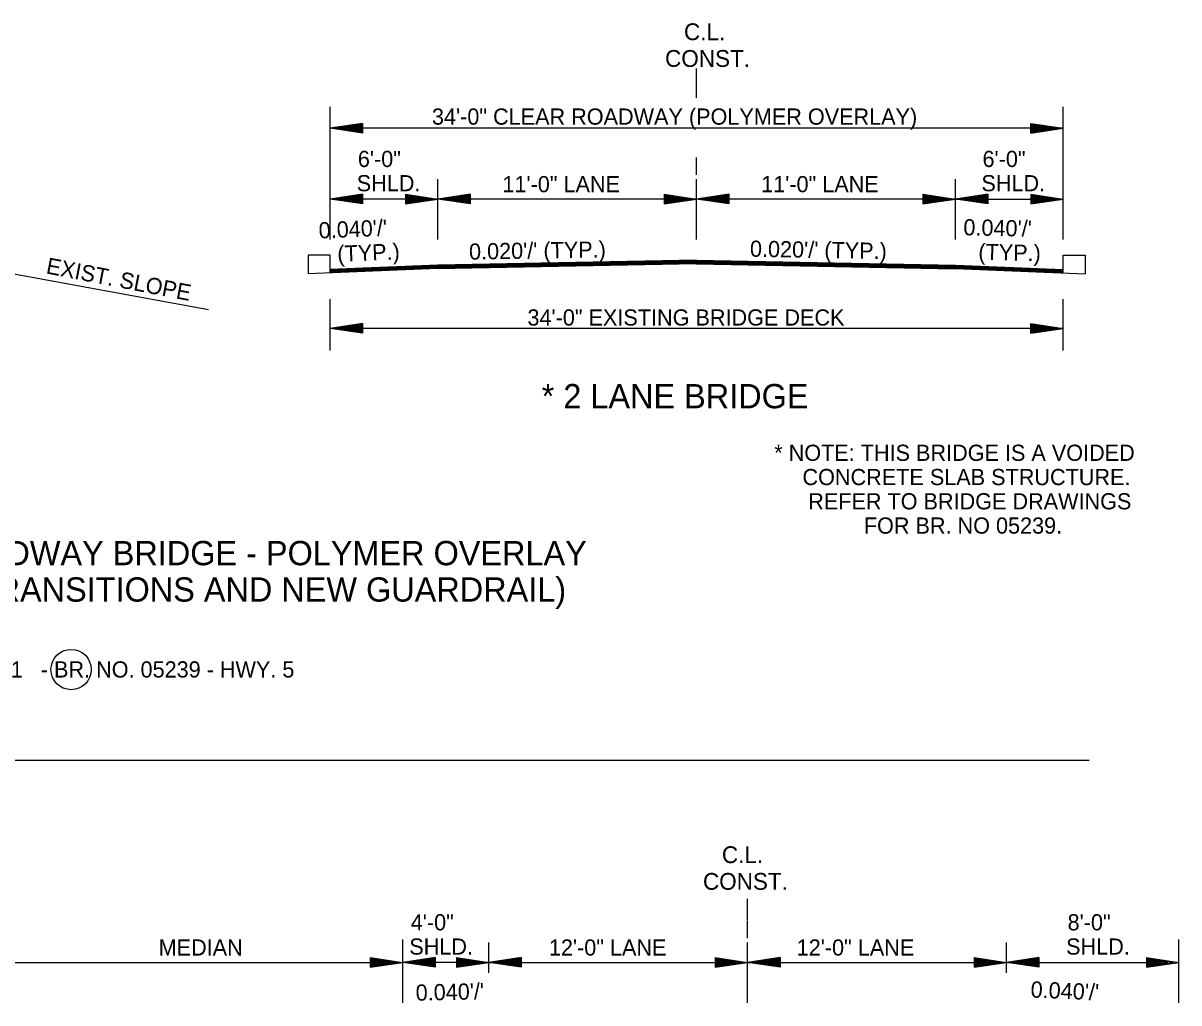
# Model space of a CAD drawing. Extents: x 544199 to 1930787, y -1968972 to 596640.
# Drawn here: x 546713 to 547249, y -1947878 to -1947424 of the extents above; entities that cross this region are included whole.
import ezdxf

# ---------------------------------------------------------------- set-up
doc = ezdxf.new("R2010")
doc.units = 0
doc.layers.add('R_Border', color=7, linetype='Continuous')
doc.layers.add('R_Draft', color=7, linetype='Continuous')

msp = doc.modelspace()

# ---------------------------------------------------------------- linework, layer by layer
at = {"layer": 'R_Border'}
for p, q in [((546845.64, -1947531.28), (546845.64, -1947539.89)), ((546855.81, -1947531.28), (546845.64, -1947531.28)), ((546855.81, -1947539.18), (546855.81, -1947531.28)), ((547195.81, -1947539.18), (547195.81, -1947531.28)), ((547195.81, -1947531.28), (547205.98, -1947531.28)), ((547205.98, -1947531.28), (547205.98, -1947539.89)), ((546249.01, -1947765.5), (547207.84, -1947765.5))]:
    msp.add_line(p, q, dxfattribs=at)
msp.add_circle((546735.71, -1947723.42), 9.34, dxfattribs=at)
at = {"layer": 'R_Draft'}
for p, q in [((547025.81, -1947458.4), (547025.81, -1947444.7)), ((546855.81, -1947524.04), (546855.81, -1947462.55)), ((547195.81, -1947524.04), (547195.81, -1947462.55)), ((546870.81, -1947470.19), (546855.81, -1947472.44)), ((547195.81, -1947472.44), (546855.81, -1947472.44)), ((546870.81, -1947474.69), (546855.81, -1947472.44)), ((546870.81, -1947470.57), (546858.31, -1947472.44)), ((546870.81, -1947474.32), (546858.31, -1947472.44)), ((546870.81, -1947470.95), (546860.89, -1947472.44)), ((546870.81, -1947473.93), (546860.89, -1947472.44)), ((546870.81, -1947471.32), (546863.39, -1947472.44)), ((546870.81, -1947473.56), (546863.39, -1947472.44)), ((546870.81, -1947471.71), (546865.93, -1947472.44)), ((546870.81, -1947473.18), (546865.93, -1947472.44)), ((546870.81, -1947472.09), (546868.44, -1947472.44)), ((546870.81, -1947472.79), (546868.44, -1947472.44)), ((546870.81, -1947470.19), (546870.81, -1947474.69)), ((547195.81, -1947472.44), (546915.81, -1947472.44)), ((547180.81, -1947470.19), (547195.81, -1947472.44)), ((547180.81, -1947474.69), (547180.81, -1947470.19)), ((547180.81, -1947470.57), (547193.3, -1947472.44)), ((547180.81, -1947470.95), (547190.72, -1947472.44)), ((547180.81, -1947471.32), (547188.23, -1947472.44)), ((547180.81, -1947471.71), (547185.68, -1947472.44)), ((547180.81, -1947472.09), (547183.18, -1947472.44)), ((547180.81, -1947474.69), (547195.81, -1947472.44)), ((547180.81, -1947473.17), (547185.68, -1947472.44)), ((547180.81, -1947473.93), (547190.72, -1947472.44)), ((547180.81, -1947474.32), (547193.3, -1947472.44)), ((547180.81, -1947473.56), (547188.23, -1947472.44)), ((547180.81, -1947472.79), (547183.18, -1947472.44)), ((547025.81, -1947493.96), (547025.81, -1947485.98)), ((546905.81, -1947524.04), (546905.81, -1947496.09)), ((547025.81, -1947524.04), (547025.81, -1947496.09)), ((547145.81, -1947524.04), (547145.81, -1947496.09)), ((546870.81, -1947503.02), (546855.81, -1947505.27)), ((546905.81, -1947505.27), (546855.81, -1947505.27)), ((546870.81, -1947507.52), (546855.81, -1947505.27)), ((546870.81, -1947503.4), (546858.31, -1947505.27)), ((546870.81, -1947507.15), (546858.31, -1947505.27)), ((546870.81, -1947503.78), (546860.89, -1947505.27)), ((546870.81, -1947506.77), (546860.89, -1947505.27)), ((546870.81, -1947504.16), (546863.39, -1947505.27)), ((546870.81, -1947506.39), (546863.39, -1947505.27)), ((546870.81, -1947504.55), (546865.93, -1947505.27)), ((546870.81, -1947506.01), (546865.93, -1947505.27)), ((546870.81, -1947504.92), (546868.44, -1947505.27)), ((546870.81, -1947505.63), (546868.44, -1947505.27)), ((546870.81, -1947503.02), (546870.81, -1947507.52)), ((546890.81, -1947503.02), (546905.81, -1947505.27)), ((546890.81, -1947503.02), (546890.81, -1947507.52)), ((546890.81, -1947503.4), (546903.3, -1947505.27)), ((546890.81, -1947503.78), (546900.72, -1947505.27)), ((546890.81, -1947504.16), (546898.23, -1947505.27)), ((546890.81, -1947504.55), (546895.68, -1947505.27)), ((546890.81, -1947504.92), (546893.18, -1947505.27)), ((546890.81, -1947507.52), (546905.81, -1947505.27)), ((546890.81, -1947506.01), (546895.68, -1947505.27)), ((546890.81, -1947506.77), (546900.72, -1947505.27)), ((546890.81, -1947507.15), (546903.3, -1947505.27)), ((546890.81, -1947506.39), (546898.23, -1947505.27)), ((546890.81, -1947505.63), (546893.18, -1947505.27)), ((546920.81, -1947503.02), (546905.81, -1947505.27)), ((547025.81, -1947505.27), (546905.81, -1947505.27)), ((546920.81, -1947507.52), (546905.81, -1947505.27)), ((546920.81, -1947503.4), (546908.31, -1947505.27)), ((546920.81, -1947507.15), (546908.31, -1947505.27)), ((546920.81, -1947503.78), (546910.89, -1947505.27)), ((546920.81, -1947506.77), (546910.89, -1947505.27)), ((546920.81, -1947504.16), (546913.39, -1947505.27)), ((546920.81, -1947506.39), (546913.39, -1947505.27)), ((546920.81, -1947504.55), (546915.93, -1947505.27)), ((546920.81, -1947506.01), (546915.93, -1947505.27)), ((546920.81, -1947504.92), (546918.44, -1947505.27)), ((546920.81, -1947505.63), (546918.44, -1947505.27)), ((546920.81, -1947503.02), (546920.81, -1947507.52)), ((547010.81, -1947503.02), (547025.81, -1947505.27)), ((547010.81, -1947503.02), (547010.81, -1947507.52)), ((547010.81, -1947503.4), (547023.3, -1947505.27)), ((547010.81, -1947503.78), (547020.72, -1947505.27)), ((547010.81, -1947504.16), (547018.23, -1947505.27)), ((547010.81, -1947504.55), (547015.68, -1947505.27)), ((547010.81, -1947504.92), (547013.18, -1947505.27)), ((547010.81, -1947507.52), (547025.81, -1947505.27)), ((547010.81, -1947506.01), (547015.68, -1947505.27)), ((547010.81, -1947506.77), (547020.72, -1947505.27)), ((547010.81, -1947507.15), (547023.3, -1947505.27)), ((547010.81, -1947506.39), (547018.23, -1947505.27)), ((547010.81, -1947505.63), (547013.18, -1947505.27)), ((547040.81, -1947503.02), (547025.81, -1947505.27)), ((547145.81, -1947505.27), (547025.81, -1947505.27)), ((547040.81, -1947507.52), (547025.81, -1947505.27)), ((547040.81, -1947503.4), (547028.31, -1947505.27)), ((547040.81, -1947507.15), (547028.31, -1947505.27)), ((547040.81, -1947503.78), (547030.89, -1947505.27)), ((547040.81, -1947506.77), (547030.89, -1947505.27)), ((547040.81, -1947504.16), (547033.39, -1947505.27)), ((547040.81, -1947506.39), (547033.39, -1947505.27)), ((547040.81, -1947504.55), (547035.93, -1947505.27)), ((547040.81, -1947506.01), (547035.93, -1947505.27)), ((547040.81, -1947504.92), (547038.44, -1947505.27)), ((547040.81, -1947505.63), (547038.44, -1947505.27)), ((547040.81, -1947503.02), (547040.81, -1947507.52)), ((547130.81, -1947503.02), (547145.81, -1947505.27)), ((547130.81, -1947503.02), (547130.81, -1947507.52)), ((547130.81, -1947503.4), (547143.3, -1947505.27)), ((547130.81, -1947503.78), (547140.72, -1947505.27)), ((547130.81, -1947504.16), (547138.23, -1947505.27)), ((547130.81, -1947504.55), (547135.68, -1947505.27)), ((547130.81, -1947504.92), (547133.18, -1947505.27)), ((547130.81, -1947507.52), (547145.81, -1947505.27)), ((547130.81, -1947506.01), (547135.68, -1947505.27)), ((547130.81, -1947506.77), (547140.72, -1947505.27)), ((547130.81, -1947507.15), (547143.3, -1947505.27)), ((547130.81, -1947506.39), (547138.23, -1947505.27)), ((547130.81, -1947505.63), (547133.18, -1947505.27)), ((547160.81, -1947503.02), (547145.81, -1947505.27)), ((547145.81, -1947505.27), (547195.81, -1947505.27)), ((547160.81, -1947507.52), (547145.81, -1947505.27)), ((547160.81, -1947503.4), (547148.31, -1947505.27)), ((547160.81, -1947507.15), (547148.31, -1947505.27)), ((547160.81, -1947503.78), (547150.89, -1947505.27)), ((547160.81, -1947506.77), (547150.89, -1947505.27)), ((547160.81, -1947504.16), (547153.39, -1947505.27)), ((547160.81, -1947506.39), (547153.39, -1947505.27)), ((547160.81, -1947504.55), (547155.93, -1947505.27)), ((547160.81, -1947506.01), (547155.93, -1947505.27)), ((547160.81, -1947504.92), (547158.44, -1947505.27)), ((547160.81, -1947505.63), (547158.44, -1947505.27)), ((547160.81, -1947503.02), (547160.81, -1947507.52)), ((547180.81, -1947503.02), (547195.81, -1947505.27)), ((547180.81, -1947503.02), (547180.81, -1947507.52)), ((547180.81, -1947503.4), (547193.3, -1947505.27)), ((547180.81, -1947503.78), (547190.72, -1947505.27)), ((547180.81, -1947504.16), (547188.23, -1947505.27)), ((547180.81, -1947504.55), (547185.68, -1947505.27)), ((547180.81, -1947504.92), (547183.18, -1947505.27)), ((547180.81, -1947507.52), (547195.81, -1947505.27)), ((547180.81, -1947506.01), (547185.68, -1947505.27)), ((547180.81, -1947506.77), (547190.72, -1947505.27)), ((547180.81, -1947507.15), (547193.3, -1947505.27)), ((547180.81, -1947506.39), (547188.23, -1947505.27)), ((547180.81, -1947505.63), (547183.18, -1947505.27)), ((547025.81, -1947533.58), (546905.81, -1947535.98)), ((547025.81, -1947533.88), (546905.81, -1947536.28)), ((547025.81, -1947533.58), (547145.81, -1947535.98)), ((547025.81, -1947533.88), (547145.81, -1947536.28)), ((546699.39, -1947538.09), (546799.46, -1947556.47)), ((546905.81, -1947537.48), (546845.64, -1947539.89)), ((546905.81, -1947535.98), (546855.81, -1947537.98)), ((546905.81, -1947536.28), (546855.81, -1947538.28)), ((546905.81, -1947536.58), (546855.81, -1947538.58)), ((546905.81, -1947536.88), (546855.81, -1947538.88)), ((546905.81, -1947537.18), (546855.81, -1947539.18)), ((547025.81, -1947534.18), (546905.81, -1947536.58)), ((547025.81, -1947534.48), (546905.81, -1947536.88)), ((547025.81, -1947534.78), (546905.81, -1947537.18)), ((547025.81, -1947535.08), (546905.81, -1947537.48)), ((547025.81, -1947535.25), (546905.81, -1947537.65)), ((547025.81, -1947534.18), (547145.81, -1947536.58)), ((547025.81, -1947534.48), (547145.81, -1947536.88)), ((547025.81, -1947534.78), (547145.81, -1947537.18)), ((547025.81, -1947535.08), (547145.81, -1947537.48)), ((547025.81, -1947535.25), (547145.81, -1947537.65)), ((547145.81, -1947535.98), (547195.81, -1947537.98)), ((547145.81, -1947536.28), (547195.81, -1947538.28)), ((547145.81, -1947536.58), (547195.81, -1947538.58)), ((547145.81, -1947536.88), (547195.81, -1947538.88)), ((547145.81, -1947537.18), (547195.81, -1947539.18)), ((547145.81, -1947537.48), (547205.98, -1947539.89)), ((546855.84, -1947575.42), (546855.84, -1947551.73)), ((547195.83, -1947575.42), (547195.83, -1947551.73)), ((546870.81, -1947562.99), (546855.81, -1947565.24)), ((546870.81, -1947567.49), (546855.81, -1947565.24)), ((547195.81, -1947565.24), (546855.81, -1947565.24)), ((546870.81, -1947563.37), (546858.31, -1947565.24)), ((546870.81, -1947567.12), (546858.31, -1947565.24)), ((546870.81, -1947563.75), (546860.89, -1947565.24)), ((546870.81, -1947566.74), (546860.89, -1947565.24)), ((546870.81, -1947564.13), (546863.39, -1947565.24)), ((546870.81, -1947566.36), (546863.39, -1947565.24)), ((546870.81, -1947564.52), (546865.93, -1947565.24)), ((546870.81, -1947565.98), (546865.93, -1947565.24)), ((546870.81, -1947564.89), (546868.44, -1947565.24)), ((546870.81, -1947565.6), (546868.44, -1947565.24)), ((546870.81, -1947562.99), (546870.81, -1947567.49)), ((547180.81, -1947562.99), (547195.81, -1947565.24)), ((547180.81, -1947567.49), (547180.81, -1947562.99)), ((547180.81, -1947563.37), (547193.3, -1947565.24)), ((547180.81, -1947563.75), (547190.72, -1947565.24)), ((547180.81, -1947564.13), (547188.23, -1947565.24)), ((547180.81, -1947564.51), (547185.68, -1947565.24)), ((547180.81, -1947564.89), (547183.18, -1947565.24)), ((547180.81, -1947567.49), (547195.81, -1947565.24)), ((547180.81, -1947565.97), (547185.68, -1947565.24)), ((547180.81, -1947566.74), (547190.72, -1947565.24)), ((547180.81, -1947567.12), (547193.3, -1947565.24)), ((547180.81, -1947566.36), (547188.23, -1947565.24)), ((547180.81, -1947565.6), (547183.18, -1947565.24)), ((547049.49, -1947839.58), (547049.49, -1947829.77)), ((547049.49, -1947847.91), (547049.49, -1947839.93)), ((546889.49, -1947877.99), (546889.49, -1947848.64)), ((546929.49, -1947864.01), (546929.49, -1947850.04)), ((547049.49, -1947877.99), (547049.49, -1947850.04)), ((547169.49, -1947864.01), (547169.49, -1947850.04)), ((547249.49, -1947877.99), (547249.49, -1947848.64)), ((546698.19, -1947859.23), (546889.49, -1947859.23)), ((546874.49, -1947856.98), (546889.49, -1947859.23)), ((546874.49, -1947856.98), (546874.49, -1947861.48)), ((546874.49, -1947857.35), (546886.98, -1947859.23)), ((546874.49, -1947857.73), (546884.4, -1947859.23)), ((546874.49, -1947858.11), (546881.9, -1947859.23)), ((546874.49, -1947858.5), (546879.36, -1947859.23)), ((546874.49, -1947858.87), (546876.86, -1947859.23)), ((546874.49, -1947861.48), (546889.49, -1947859.23)), ((546874.49, -1947859.96), (546879.36, -1947859.23)), ((546874.49, -1947860.72), (546884.4, -1947859.23)), ((546874.49, -1947861.1), (546886.98, -1947859.23)), ((546874.49, -1947860.34), (546881.9, -1947859.23)), ((546874.49, -1947859.58), (546876.86, -1947859.23)), ((546904.49, -1947856.98), (546889.49, -1947859.23)), ((546929.49, -1947859.23), (546889.49, -1947859.23)), ((546904.49, -1947861.48), (546889.49, -1947859.23)), ((546904.49, -1947857.35), (546891.99, -1947859.23)), ((546904.49, -1947861.1), (546891.99, -1947859.23)), ((546904.49, -1947857.73), (546894.57, -1947859.23)), ((546904.49, -1947860.72), (546894.57, -1947859.23)), ((546904.49, -1947858.11), (546897.07, -1947859.23)), ((546904.49, -1947860.34), (546897.07, -1947859.23)), ((546904.49, -1947858.5), (546899.61, -1947859.23)), ((546904.49, -1947859.96), (546899.61, -1947859.23)), ((546904.49, -1947858.87), (546902.12, -1947859.23)), ((546904.49, -1947859.58), (546902.12, -1947859.23)), ((546904.49, -1947856.98), (546904.49, -1947861.48)), ((546914.49, -1947856.98), (546929.49, -1947859.23)), ((546914.49, -1947856.98), (546914.49, -1947861.48)), ((546914.49, -1947857.35), (546926.98, -1947859.23)), ((546914.49, -1947857.73), (546924.4, -1947859.23)), ((546914.49, -1947858.11), (546921.9, -1947859.23)), ((546914.49, -1947858.5), (546919.36, -1947859.23)), ((546914.49, -1947858.87), (546916.86, -1947859.23)), ((546914.49, -1947861.48), (546929.49, -1947859.23)), ((546914.49, -1947859.96), (546919.36, -1947859.23)), ((546914.49, -1947860.72), (546924.4, -1947859.23)), ((546914.49, -1947861.1), (546926.98, -1947859.23)), ((546914.49, -1947860.34), (546921.9, -1947859.23)), ((546914.49, -1947859.58), (546916.86, -1947859.23)), ((546944.49, -1947856.98), (546929.49, -1947859.23)), ((546929.49, -1947859.23), (547049.49, -1947859.23)), ((546944.49, -1947861.48), (546929.49, -1947859.23)), ((546944.49, -1947857.35), (546931.99, -1947859.23)), ((546944.49, -1947861.1), (546931.99, -1947859.23)), ((546944.49, -1947857.73), (546934.57, -1947859.23)), ((546944.49, -1947860.72), (546934.57, -1947859.23)), ((546944.49, -1947858.11), (546937.07, -1947859.23)), ((546944.49, -1947860.34), (546937.07, -1947859.23)), ((546944.49, -1947858.5), (546939.61, -1947859.23)), ((546944.49, -1947859.96), (546939.61, -1947859.23)), ((546944.49, -1947858.87), (546942.12, -1947859.23)), ((546944.49, -1947859.58), (546942.12, -1947859.23)), ((546944.49, -1947856.98), (546944.49, -1947861.48)), ((547034.49, -1947856.98), (547049.49, -1947859.23)), ((547034.49, -1947856.98), (547034.49, -1947861.48)), ((547034.49, -1947857.35), (547046.98, -1947859.23)), ((547034.49, -1947857.73), (547044.4, -1947859.23)), ((547034.49, -1947858.11), (547041.9, -1947859.23)), ((547034.49, -1947858.5), (547039.36, -1947859.23)), ((547034.49, -1947858.87), (547036.86, -1947859.23)), ((547034.49, -1947861.48), (547049.49, -1947859.23)), ((547034.49, -1947859.96), (547039.36, -1947859.23)), ((547034.49, -1947860.72), (547044.4, -1947859.23)), ((547034.49, -1947861.1), (547046.98, -1947859.23)), ((547034.49, -1947860.34), (547041.9, -1947859.23)), ((547034.49, -1947859.58), (547036.86, -1947859.23)), ((547064.49, -1947856.98), (547049.49, -1947859.23)), ((547049.49, -1947859.23), (547169.49, -1947859.23)), ((547064.49, -1947861.48), (547049.49, -1947859.23)), ((547064.49, -1947857.35), (547051.99, -1947859.23)), ((547064.49, -1947861.1), (547051.99, -1947859.23)), ((547064.49, -1947857.73), (547054.57, -1947859.23)), ((547064.49, -1947860.72), (547054.57, -1947859.23)), ((547064.49, -1947858.11), (547057.07, -1947859.23)), ((547064.49, -1947860.34), (547057.07, -1947859.23)), ((547064.49, -1947858.5), (547059.61, -1947859.23)), ((547064.49, -1947859.96), (547059.61, -1947859.23)), ((547064.49, -1947858.87), (547062.12, -1947859.23)), ((547064.49, -1947859.58), (547062.12, -1947859.23)), ((547064.49, -1947856.98), (547064.49, -1947861.48)), ((547154.49, -1947856.98), (547169.49, -1947859.23)), ((547154.49, -1947856.98), (547154.49, -1947861.48)), ((547154.49, -1947857.35), (547166.98, -1947859.23)), ((547154.49, -1947857.73), (547164.4, -1947859.23)), ((547154.49, -1947858.11), (547161.9, -1947859.23)), ((547154.49, -1947858.5), (547159.36, -1947859.23)), ((547154.49, -1947858.87), (547156.86, -1947859.23)), ((547154.49, -1947861.48), (547169.49, -1947859.23)), ((547154.49, -1947859.96), (547159.36, -1947859.23)), ((547154.49, -1947860.72), (547164.4, -1947859.23)), ((547154.49, -1947861.1), (547166.98, -1947859.23)), ((547154.49, -1947860.34), (547161.9, -1947859.23)), ((547154.49, -1947859.58), (547156.86, -1947859.23)), ((547184.49, -1947856.98), (547169.49, -1947859.23)), ((547169.49, -1947859.23), (547239.49, -1947859.23)), ((547184.49, -1947861.48), (547169.49, -1947859.23)), ((547184.49, -1947857.35), (547171.99, -1947859.23)), ((547184.49, -1947861.1), (547171.99, -1947859.23)), ((547184.49, -1947857.73), (547174.57, -1947859.23)), ((547184.49, -1947860.72), (547174.57, -1947859.23)), ((547184.49, -1947858.11), (547177.07, -1947859.23)), ((547184.49, -1947860.34), (547177.07, -1947859.23)), ((547184.49, -1947858.5), (547179.61, -1947859.23)), ((547184.49, -1947859.96), (547179.61, -1947859.23)), ((547184.49, -1947858.87), (547182.12, -1947859.23)), ((547184.49, -1947859.58), (547182.12, -1947859.23)), ((547184.49, -1947856.98), (547184.49, -1947861.48)), ((547234.49, -1947856.98), (547249.49, -1947859.23)), ((547234.49, -1947856.98), (547234.49, -1947861.48)), ((547234.49, -1947857.35), (547246.98, -1947859.23)), ((547234.49, -1947857.73), (547244.4, -1947859.23)), ((547234.49, -1947858.11), (547241.9, -1947859.23)), ((547234.49, -1947858.5), (547239.36, -1947859.23)), ((547234.49, -1947858.87), (547236.86, -1947859.23)), ((547234.49, -1947861.48), (547249.49, -1947859.23)), ((547234.49, -1947859.96), (547239.36, -1947859.23)), ((547234.49, -1947860.72), (547244.4, -1947859.23)), ((547234.49, -1947861.1), (547246.98, -1947859.23)), ((547234.49, -1947860.34), (547241.9, -1947859.23)), ((547234.49, -1947859.58), (547236.86, -1947859.23))]:
    msp.add_line(p, q, dxfattribs=at)

# ---------------------------------------------------------------- texts
for s, height, p in [('C.L.', 7.8, (547019.96, -1947431.6)), ('CONST.', 7.8, (547011.18, -1947443.97)), ('34\'-0" CLEAR ROADWAY (POLYMER OVERLAY)', 7.5, (546903.07, -1947470.77)), ('6\'-0"', 7.5, (546868.7, -1947490.41)), ('6\'-0"', 7.5, (547158.41, -1947490.41)), ('SHLD.', 7.5, (546868.19, -1947501.66)), ('11\'-0" LANE', 7.5, (546935.75, -1947502.1)), ('11\'-0" LANE', 7.5, (547055.75, -1947502.1)), ('SHLD.', 7.5, (547157.91, -1947501.66)), ('34\'-0" EXISTING BRIDGE DECK', 7.5, (546947.36, -1947563.92)), ('* 2 LANE BRIDGE', 11.25, (546953.97, -1947602.28)), ('* NOTE: THIS BRIDGE IS A VOIDED', 7.5, (547061.83, -1947626.66)), ('CONCRETE SLAB STRUCTURE.', 7.5, (547074.91, -1947637.91)), ('REFER TO BRIDGE DRAWINGS', 7.5, (547077.57, -1947649.16)), ('FOR BR. NO 05239.', 7.5, (547103.38, -1947660.41)), ('34 FT. CLEAR ROADWAY BRIDGE - POLYMER OVERLAY', 11.25, (546571.12, -1947675.06)), ('(ROADWAY TRANSITIONS AND NEW GUARDRAIL)', 11.25, (546605.05, -1947691.93)), ('      1   - BR. NO. 05239 - HWY. 5', 7.5, (546691.02, -1947727.12)), ('C.L.', 7.8, (547037.54, -1947813.18)), ('CONST.', 7.8, (547028.76, -1947825.55)), ('4\'-0"', 7.5, (546893.24, -1947844.36)), ('8\'-0"', 7.5, (547197.87, -1947844.36)), ('MEDIAN ', 7.5, (546776.31, -1947856.05)), ('SHLD.', 7.5, (546892.56, -1947855.61)), ('12\'-0" LANE', 7.5, (546957.3, -1947856.05)), ('12\'-0" LANE', 7.5, (547072.22, -1947856.05)), ('SHLD.', 7.5, (547197.19, -1947855.61))]:
    msp.add_text(s, height=height, dxfattribs=at).set_placement(p)
for s, rotation, p in [("  0.040'/'", 2.448, (546845.12, -1947523.81)), ("0.040'/'", 358.6816, (547149.48, -1947522.03)), (' (TYP.)', 2.448, (546856.55, -1947534.58)), ("0.020'/' (TYP.)", 0.9719, (546920.33, -1947533.38)), ("0.020'/' (TYP.)", 359.0281, (547050.51, -1947532.01)), ('(TYP.)', 358.6816, (547156.42, -1947533.44)), ('EXIST. SLOPE', 349.1171, (546723.77, -1947539.69)), ("0.040'/'", 1.3184, (546895.6, -1947877.01)), ("  0.040'/'", 357.552, (547175.03, -1947875.22))]:
    msp.add_text(s, height=7.5, rotation=rotation, dxfattribs=at).set_placement(p)

doc.saveas('drawing.dxf')
